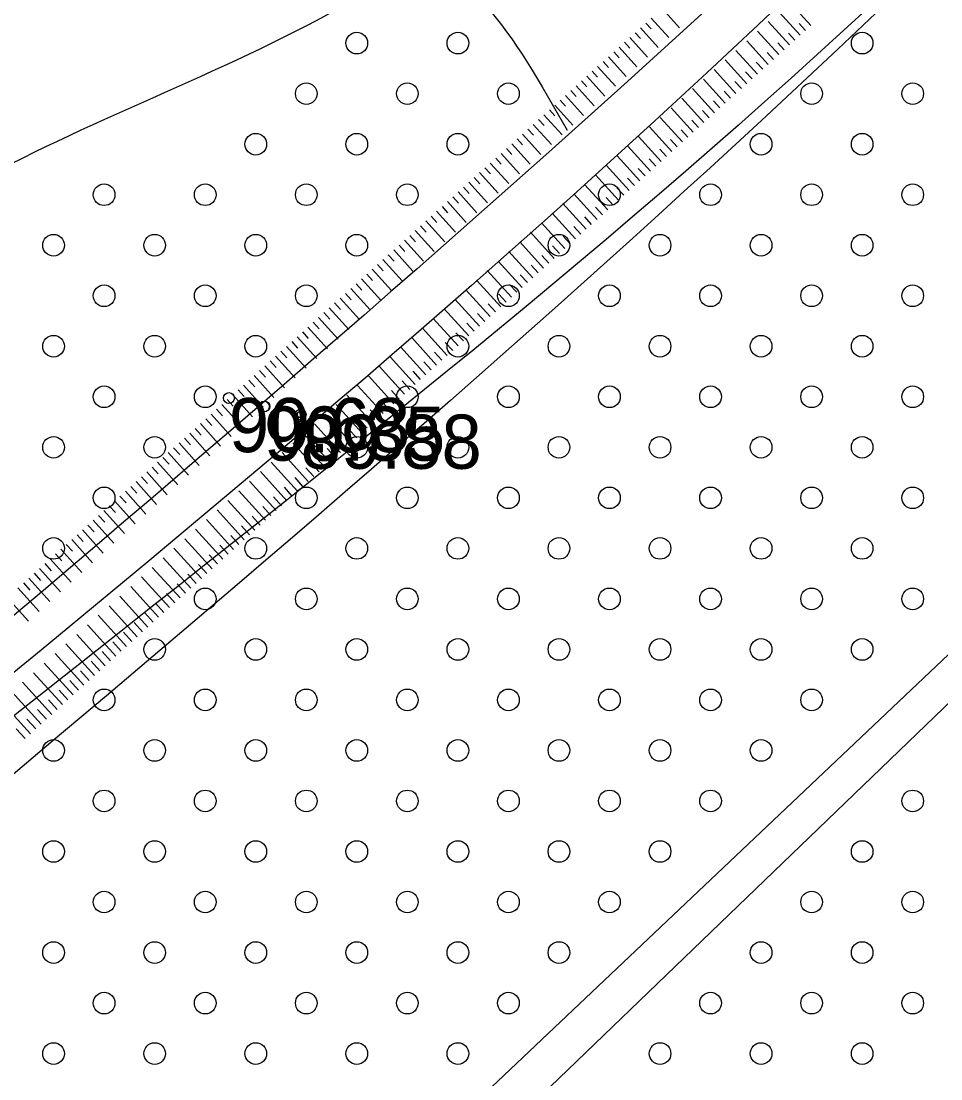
# Model space of a CAD drawing. Extents: x 316000 to 728450, y 314368 to 726000.
# Drawn here: x 725638.8 to 725702.4, y 315523.2 to 315596.5 of the extents above; entities that cross this region are included whole.
import ezdxf

# ---------------------------------------------------------------- set-up
doc = ezdxf.new("R2010")
doc.units = 0
for name, color, linetype in [('HIDG_ELEM_####_####_#', 7, 'Continuous'), ('HIDG_GRAV_####_####_#', 7, 'Continuous'), ('RELJ_AATZ_####_TKST_#', 7, 'Continuous'), ('RELJ_ELEM_####_####_#', 7, 'Continuous'), ('RELJ_NOGA_####_####_#', 7, 'Continuous'), ('TERT_ELEM_####_####_#', 7, 'Continuous'), ('TERT_KONT_####_####_#', 7, 'Continuous')]:
    doc.layers.add(name, color=color, linetype=linetype)

msp = doc.modelspace()

# ---------------------------------------------------------------- linework, layer by layer
at = {"layer": 'HIDG_ELEM_####_####_#'}
msp.add_circle((725658.106, 315569.264), 0.225, dxfattribs=at)
at = {"layer": 'HIDG_GRAV_####_####_#'}
msp.add_lwpolyline([(725748.973, 315596.209), (725751.0100204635, 315595.5121681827), (725643.1476843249, 315491.6312040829), (725641.4060000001, 315494.343), (725748.973, 315596.209)], dxfattribs=at)
for points in [[(725743.944, 315631.872), (725731.1800000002, 315638.5140000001), (725730.0588248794, 315638.4860084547), (725729.0416291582, 315637.5281018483), (725728.0741186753, 315636.1890738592), (725727.1019992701, 315635.017718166), (725611.6787771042, 315529.82054677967)], [(725741.1610000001, 315628.109), (725732.013, 315633.48000000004), (725729.3674430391, 315630.93907173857), (725612.6699933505, 315527.51301727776), (725555.2138402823, 315474.3075427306)]]:
    msp.add_spline(points, degree=3, dxfattribs=at)
at = {"layer": 'RELJ_ELEM_####_####_#'}
for centre in [(725653.1460000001, 315570.414), (725655.572, 315569.825), (725655.606, 315569.829), (725658.106, 315569.264)]:
    msp.add_circle(centre, 0.375, dxfattribs=at)
at = {"layer": 'RELJ_NOGA_####_####_#'}
for p, q in [((725683.1404815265, 315597.39670044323), (725684.3494049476, 315596.05283824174)), ((725693.4445708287, 315596.2198231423), (725691.9950560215, 315597.8168523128)), ((725682.3970354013, 315596.72790461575), (725683.6103007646, 315595.3792158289)), ((725692.7040932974, 315595.547742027), (725691.2466238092, 315597.1535354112)), ((725681.653589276, 315596.05910878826), (725682.8711965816, 315594.7055934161)), ((725682.0253123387, 315596.39350670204), (725682.3899432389, 315595.9881760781)), ((725691.2231382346, 315594.2035797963), (725689.7497593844, 315595.82690160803)), ((725691.963615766, 315594.8756609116), (725690.4981915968, 315596.4902185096)), ((725693.0743320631, 315595.88378258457), (725692.6382844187, 315596.3642059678)), ((725680.5384200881, 315595.055915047), (725680.9056561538, 315594.64768847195)), ((725680.9101431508, 315595.3903129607), (725682.1320923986, 315594.0319710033)), ((725681.2818662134, 315595.7247108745), (725681.6477996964, 315595.317932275)), ((725690.4826607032, 315593.53149868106), (725689.0013271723, 315595.1635847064)), ((725692.3338545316, 315595.2117014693), (725691.8954204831, 315595.69475411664)), ((725679.7949739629, 315594.3871192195), (725680.1635126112, 315593.9774446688)), ((725680.1666970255, 315594.72151713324), (725681.3929882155, 315593.3583485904)), ((725689.7421831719, 315592.85941756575), (725688.2528949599, 315594.50026780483)), ((725690.852899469, 315593.8675392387), (725690.4096926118, 315594.35585041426)), ((725691.5933770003, 315594.539620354), (725691.1525565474, 315595.0253022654)), ((725679.0515278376, 315593.71832339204), (725679.4213690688, 315593.30720086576)), ((725679.4232509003, 315594.05272130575), (725680.6538840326, 315592.6847261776)), ((725689.0017056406, 315592.18733645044), (725687.5044627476, 315593.83695090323)), ((725690.1124219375, 315593.1954581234), (725689.666828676, 315593.6863985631)), ((725678.3080817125, 315593.0495275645), (725678.6792255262, 315592.63695706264)), ((725678.679804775, 315593.38392547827), (725679.9147798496, 315592.01110376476)), ((725688.2612281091, 315591.51525533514), (725686.7560305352, 315593.1736340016)), ((725689.3719444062, 315592.5233770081), (725688.9239647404, 315593.01694671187)), ((725677.5646355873, 315592.380731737), (725677.9370819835, 315591.9667132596)), ((725677.9363586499, 315592.7151296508), (725679.1756756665, 315591.337481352)), ((725687.5207505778, 315590.8431742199), (725686.0075983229, 315592.51031710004)), ((725688.6314668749, 315591.8512958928), (725688.1811008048, 315592.34749486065)), ((725676.821189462, 315591.7119359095), (725677.194938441, 315591.2964694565)), ((725677.1929125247, 315592.0463338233), (725678.4365714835, 315590.66385893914)), ((725686.7802730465, 315590.1710931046), (725685.2591661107, 315591.84700019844)), ((725687.8909893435, 315591.1792147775), (725687.4382368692, 315591.6780430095)), ((725675.7060202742, 315590.7087421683), (725676.9583631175, 315589.3166141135)), ((725676.0777433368, 315591.04314008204), (725676.4527948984, 315590.62622565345)), ((725676.4494663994, 315591.3775379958), (725677.6974673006, 315589.9902365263)), ((725686.039795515, 315589.4990119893), (725684.5107338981, 315591.18368329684)), ((725687.1505118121, 315590.5071336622), (725686.6953729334, 315591.0085911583)), ((725674.962574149, 315590.0399463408), (725676.2192589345, 315588.64299170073)), ((725675.3342972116, 315590.3743442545), (725675.7106513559, 315589.95598185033)), ((725685.2993179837, 315588.8269308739), (725683.762301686, 315590.5203663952)), ((725686.4100342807, 315589.83505254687), (725685.9525089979, 315590.33913930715)), ((725674.2191280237, 315589.3711505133), (725675.4801547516, 315587.9693692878)), ((725674.5908510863, 315589.705548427), (725674.9685078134, 315589.2857380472)), ((725683.8183629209, 315587.48276864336), (725682.2654372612, 315589.193732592)), ((725684.5588404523, 315588.15484975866), (725683.0138694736, 315589.85704949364)), ((725685.6695567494, 315589.1629714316), (725685.2096450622, 315589.6696874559)), ((725673.4756818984, 315588.7023546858), (725674.7410505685, 315587.295746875)), ((725673.847404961, 315589.0367525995), (725674.2263642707, 315588.6154942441)), ((725683.0778853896, 315586.81068752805), (725681.5170050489, 315588.5304156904)), ((725684.929079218, 315588.4908903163), (725684.4667811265, 315589.0002356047)), ((725672.7322357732, 315588.0335588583), (725674.0019463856, 315586.62212446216)), ((725673.1039588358, 315588.36795677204), (725673.4842207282, 315587.94525044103)), ((725682.3374078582, 315586.13860641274), (725680.7685728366, 315587.86709878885)), ((725684.1886016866, 315587.818809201), (725683.7239171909, 315588.33078375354)), ((725671.6170665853, 315587.03036511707), (725671.999933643, 315586.6047628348)), ((725671.988789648, 315587.3647630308), (725673.2628422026, 315585.9485020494)), ((725672.3605127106, 315587.6991609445), (725672.7420771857, 315587.2750066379)), ((725681.5969303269, 315585.46652529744), (725680.0201406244, 315587.20378188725)), ((725682.7076466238, 315586.4746469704), (725682.2381893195, 315586.99188005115)), ((725683.4481241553, 315587.1467280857), (725682.9810532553, 315587.6613319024)), ((725670.8736204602, 315586.3615692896), (725671.2577901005, 315585.9345190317)), ((725671.2453435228, 315586.6959672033), (725672.5237380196, 315585.27487963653)), ((725680.8564527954, 315584.7944441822), (725679.271708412, 315586.54046498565)), ((725681.9671690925, 315585.8025658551), (725681.4953253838, 315586.3224282)), ((725670.130174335, 315585.6927734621), (725670.5156465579, 315585.26427522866)), ((725670.5018973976, 315586.0271713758), (725671.7846338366, 315584.6012572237)), ((725680.1159752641, 315584.1223630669), (725678.5232761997, 315585.87714808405)), ((725681.2266915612, 315585.1304847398), (725680.7524614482, 315585.6529763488)), ((725669.3867282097, 315585.02397763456), (725669.7735030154, 315584.59403142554)), ((725669.7584512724, 315585.3583755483), (725671.0455296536, 315583.9276348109)), ((725679.3754977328, 315583.4502819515), (725677.7748439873, 315585.21383118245)), ((725680.4862140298, 315584.4584036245), (725680.0095975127, 315584.9835244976)), ((725668.6432820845, 315584.35518180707), (725669.0313594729, 315583.9237876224)), ((725669.0150051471, 315584.6895797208), (725670.3064254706, 315583.2540123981)), ((725678.6350202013, 315582.77820083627), (725677.0264117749, 315584.5505142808)), ((725679.7457364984, 315583.78632250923), (725679.2667335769, 315584.3140726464)), ((725667.5281128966, 315583.3519880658), (725668.8282171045, 315581.9067675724)), ((725667.8998359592, 315583.6863859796), (725668.2892159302, 315583.25354381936)), ((725668.2715590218, 315584.0207838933), (725669.5673212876, 315582.5803899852)), ((725677.89454267, 315582.10611972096), (725676.2779795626, 315583.8871973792)), ((725679.005258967, 315583.1142413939), (725678.5238696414, 315583.6446207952)), ((725666.7846667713, 315582.6831922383), (725668.0891129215, 315581.2331451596)), ((725667.156389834, 315583.0175901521), (725667.5470723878, 315582.5833000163)), ((725677.1540651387, 315581.43403860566), (725675.5295473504, 315583.22388047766)), ((725678.2647814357, 315582.4421602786), (725677.7810057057, 315582.97516894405)), ((725666.0412206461, 315582.01439641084), (725667.3500087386, 315580.5595227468)), ((725666.4129437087, 315582.3487943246), (725666.8049288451, 315581.9130562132)), ((725675.6731100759, 315580.08987637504), (725674.0326829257, 315581.8972466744)), ((725676.4135876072, 315580.76195749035), (725674.781115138, 315582.560563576)), ((725677.5243039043, 315581.7700791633), (725677.0381417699, 315582.3057170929)), ((725665.2977745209, 315581.34560058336), (725666.6109045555, 315579.88590033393)), ((725665.6694975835, 315581.6799984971), (725666.0627853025, 315581.24281241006)), ((725674.9326325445, 315579.4177952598), (725673.2842507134, 315581.2339297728)), ((725676.7838263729, 315581.09799804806), (725676.2952778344, 315581.63626524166)), ((725664.5543283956, 315580.6768047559), (725665.8718003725, 315579.2122779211)), ((725664.9260514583, 315581.0112026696), (725665.32064176, 315580.572568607)), ((725674.1921550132, 315578.7457141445), (725672.5358185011, 315580.5706128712)), ((725676.0433488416, 315580.4259169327), (725675.5524138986, 315580.96681339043)), ((725663.4391592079, 315579.6736110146), (725663.836354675, 315579.2320810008)), ((725663.8108822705, 315580.0080089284), (725665.1326961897, 315578.5386555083)), ((725664.182605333, 315580.3424068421), (725664.5784982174, 315579.9023248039)), ((725673.4516774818, 315578.0736330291), (725671.7873862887, 315579.9072959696)), ((725675.3028713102, 315579.7538358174), (725674.809549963, 315580.29736153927)), ((725662.6957130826, 315579.0048151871), (725663.0942111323, 315578.56183719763)), ((725663.0674361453, 315579.33921310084), (725664.3935920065, 315577.86503309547)), ((725672.7111999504, 315577.4015519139), (725671.0389540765, 315579.243979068)), ((725673.8219162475, 315578.40967358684), (725673.3238220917, 315578.9584578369)), ((725674.5623937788, 315579.0817547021), (725674.0666860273, 315579.62790968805)), ((725661.9522669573, 315578.3360193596), (725662.3520675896, 315577.89159339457)), ((725662.32399002, 315578.67041727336), (725663.6544878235, 315577.1914106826)), ((725671.9707224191, 315576.7294707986), (725670.2905218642, 315578.5806621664)), ((725673.0814387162, 315577.73759247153), (725672.5809581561, 315578.2890059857)), ((725661.2088208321, 315577.6672235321), (725661.6099240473, 315577.2213495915)), ((725661.5805438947, 315578.0016214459), (725662.9153836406, 315576.51778826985)), ((725671.2302448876, 315576.05738968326), (725669.5420896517, 315577.9173452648)), ((725672.3409611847, 315577.0655113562), (725671.8380942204, 315577.61955413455)), ((725660.4653747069, 315576.9984277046), (725660.8677805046, 315576.5511057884)), ((725660.8370977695, 315577.3328256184), (725662.1762794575, 315575.844165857)), ((725670.4897673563, 315575.38530856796), (725668.7936574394, 315577.25402836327)), ((725671.6004836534, 315576.3934302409), (725671.0952302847, 315576.9501022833)), ((725659.7219285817, 315576.32963187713), (725660.125636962, 315575.88086198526)), ((725660.0936516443, 315576.6640297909), (725661.4371752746, 315575.17054344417)), ((725669.749289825, 315574.71322745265), (725668.0452252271, 315576.5907114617)), ((725670.860006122, 315575.7213491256), (725670.3523663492, 315576.28065043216)), ((725658.6067593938, 315575.3264381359), (725659.9589669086, 315573.82329861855)), ((725658.9784824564, 315575.66083604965), (725659.3834934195, 315575.2106181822)), ((725659.350205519, 315575.99523396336), (725660.6980710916, 315574.4969210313)), ((725669.0088122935, 315574.0411463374), (725667.2967930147, 315575.92739456)), ((725670.1195285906, 315575.0492680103), (725669.6095024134, 315575.61119858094)), ((725657.8633132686, 315574.6576423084), (725659.2198627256, 315573.1496762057)), ((725658.2350363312, 315574.99204022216), (725658.641349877, 315574.54037437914)), ((725667.5278572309, 315572.69698410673), (725665.7999285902, 315574.6007607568)), ((725668.2683347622, 315573.3690652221), (725666.5483608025, 315575.2640776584)), ((725669.3790510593, 315574.377186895), (725668.8666384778, 315574.9417467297)), ((725657.1198671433, 315573.9888464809), (725658.4807585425, 315572.4760537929)), ((725657.491590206, 315574.3232443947), (725657.8992063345, 315573.8701305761)), ((725666.7873796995, 315572.0249029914), (725665.0514963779, 315573.9374438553)), ((725668.6385735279, 315573.7051057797), (725668.1237745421, 315574.2722948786)), ((725656.376421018, 315573.32005065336), (725657.7416543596, 315571.80243138)), ((725656.7481440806, 315573.6544485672), (725657.1570627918, 315573.19988677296)), ((725666.0469021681, 315571.3528218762), (725664.3030641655, 315573.2741269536)), ((725667.8980959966, 315573.03302466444), (725667.3809106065, 315573.6028430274)), ((725655.6329748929, 315572.6512548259), (725657.0025501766, 315571.12880896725)), ((725656.0046979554, 315572.98565273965), (725656.4149192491, 315572.52964296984)), ((725665.3064246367, 315570.6807407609), (725663.5546319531, 315572.610810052)), ((725667.1576184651, 315572.36094354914), (725666.6380466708, 315572.93339117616)), ((725654.517805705, 315571.6480610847), (725654.9306321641, 315571.18915536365)), ((725654.8895287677, 315571.9824589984), (725656.2634459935, 315570.4551865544)), ((725655.2612518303, 315572.31685691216), (725655.6727757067, 315571.8593991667)), ((725664.5659471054, 315570.00865964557), (725662.806199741, 315571.9474931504)), ((725666.4171409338, 315571.68886243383), (725665.8951827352, 315572.263939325)), ((725653.7743595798, 315570.9792652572), (725654.1884886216, 315570.5189115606)), ((725654.1460826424, 315571.3136631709), (725655.5243418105, 315569.78156414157)), ((725663.825469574, 315569.33657853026), (725662.0577675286, 315571.2841762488)), ((725664.936185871, 315570.3447002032), (725664.4094548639, 315570.9250356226)), ((725665.6766634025, 315571.0167813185), (725665.1523187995, 315571.59448747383)), ((725653.0309134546, 315570.31046942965), (725653.446345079, 315569.84866775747)), ((725653.4026365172, 315570.6448673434), (725654.7852376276, 315569.1079417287)), ((725663.0849920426, 315568.664497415), (725661.3093353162, 315570.6208593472)), ((725664.1957083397, 315569.6726190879), (725663.6665909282, 315570.25558377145)), ((725652.2874673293, 315569.64167360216), (725652.7042015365, 315569.17842395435)), ((725652.659190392, 315569.97607151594), (725654.0461334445, 315568.43431931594)), ((725662.3445145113, 315567.9924162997), (725660.5609031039, 315569.9575424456)), ((725663.4552308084, 315569.0005379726), (725662.9237269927, 315569.5861319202)), ((725651.5440212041, 315568.9728777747), (725651.962057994, 315568.5081801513)), ((725651.9157442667, 315569.30727568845), (725653.3070292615, 315567.76069690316)), ((725661.60403698, 315567.32033518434), (725659.8124708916, 315569.294225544)), ((725662.7147532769, 315568.3284568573), (725662.1808630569, 315568.91668006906)), ((725650.4288520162, 315567.9696840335), (725651.8288208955, 315566.4134520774)), ((725650.8005750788, 315568.3040819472), (725651.2199144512, 315567.8379363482)), ((725651.1722981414, 315568.63847986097), (725652.5679250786, 315567.08707449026)), ((725660.1230819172, 315565.9761729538), (725658.3156064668, 315567.96759174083)), ((725660.8635594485, 315566.64825406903), (725659.0640386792, 315568.63090864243)), ((725661.9742757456, 315567.656375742), (725661.4379991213, 315568.24722821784)), ((725649.6854058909, 315567.30088820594), (725651.0897167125, 315565.73982966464)), ((725650.0571289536, 315567.63528611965), (725650.4777709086, 315567.1676925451)), ((725659.3826043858, 315565.3040918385), (725657.5671742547, 315567.30427483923)), ((725661.2337982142, 315566.98429462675), (725660.6951351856, 315567.57777636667)), ((725648.9419597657, 315566.63209237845), (725650.3506125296, 315565.0662072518)), ((725649.3136828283, 315566.96649029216), (725649.7356273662, 315566.497448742)), ((725658.6421268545, 315564.6320107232), (725656.8187420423, 315566.6409579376)), ((725660.4933206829, 315566.31221351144), (725659.95227125, 315566.9083245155)), ((725648.1985136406, 315565.96329655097), (725649.6115083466, 315564.39258483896)), ((725648.5702367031, 315566.2976944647), (725648.9934838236, 315565.8272049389)), ((725657.9016493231, 315563.95992960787), (725656.0703098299, 315565.97764103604)), ((725659.7528431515, 315565.64013239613), (725659.2094073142, 315566.23887266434)), ((725647.4550675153, 315565.2945007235), (725648.8724041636, 315563.7189624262)), ((725647.826790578, 315565.6288986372), (725648.2513402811, 315565.15696113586)), ((725657.1611717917, 315563.2878484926), (725655.3218776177, 315565.31432413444)), ((725659.0123656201, 315564.9680512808), (725658.4665433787, 315565.5694208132)), ((725646.3398983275, 315564.2913069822), (725646.767053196, 315563.8164735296)), ((725646.7116213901, 315564.62570489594), (725648.1332999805, 315563.04534001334)), ((725647.0833444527, 315564.9601028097), (725647.5091967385, 315564.48671733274)), ((725656.4206942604, 315562.6157673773), (725654.5734454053, 315564.65100723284)), ((725658.2718880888, 315564.2959701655), (725657.723679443, 315564.8999689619)), ((725645.5964522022, 315563.62251115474), (725646.0249096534, 315563.1462297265)), ((725645.9681752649, 315563.95690906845), (725647.3941957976, 315562.3717176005)), ((725655.6802167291, 315561.94368626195), (725653.825013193, 315563.9876903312)), ((725656.7909330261, 315562.9518079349), (725656.2379515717, 315563.5610652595)), ((725657.5314105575, 315563.6238890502), (725656.9808155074, 315564.2305171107)), ((725644.853006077, 315562.95371532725), (725645.2827661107, 315562.47598592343)), ((725645.2247291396, 315563.28811324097), (725646.6550916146, 315561.6980951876)), ((725654.9397391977, 315561.27160514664), (725653.0765809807, 315563.3243734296)), ((725656.0504554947, 315562.2797268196), (725655.495087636, 315562.89161340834)), ((725644.1095599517, 315562.28491949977), (725644.5406225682, 315561.8057421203)), ((725644.4812830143, 315562.6193174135), (725645.9159874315, 315561.0244727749)), ((725654.1992616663, 315560.5995240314), (725652.3281487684, 315562.66105652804)), ((725655.3099779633, 315561.60764570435), (725654.7522237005, 315562.2221615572)), ((725643.3661138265, 315561.6161236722), (725643.7984790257, 315561.1354983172)), ((725643.7378368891, 315561.950521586), (725645.1768832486, 315560.35085036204)), ((725653.458784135, 315559.9274429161), (725651.579716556, 315561.99773962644)), ((725654.569500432, 315560.93556458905), (725654.0093597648, 315561.552709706)), ((725642.2509446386, 315560.61292993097), (725643.6986748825, 315559.00360553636)), ((725642.6226677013, 315560.94732784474), (725643.0563354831, 315560.4652545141)), ((725642.9943907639, 315561.28172575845), (725644.4377790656, 315559.6772279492)), ((725651.9778290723, 315558.5832806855), (725650.0828521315, 315560.67110582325)), ((725652.7183066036, 315559.2553618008), (725650.8312843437, 315561.3344227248)), ((725653.8290229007, 315560.26348347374), (725653.2664958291, 315560.8832578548)), ((725641.5074985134, 315559.9441341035), (725642.9595706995, 315558.3299831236)), ((725641.879221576, 315560.27853201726), (725642.3141919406, 315559.79501071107)), ((725651.2373515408, 315557.91119957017), (725649.3344199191, 315560.0077889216)), ((725653.0885453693, 315559.5914023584), (725652.5236318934, 315560.21380600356)), ((725640.7640523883, 315559.275338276), (725642.2204665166, 315557.6563607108)), ((725641.1357754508, 315559.60973618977), (725641.572048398, 315559.124766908)), ((725650.4968740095, 315557.2391184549), (725648.5859877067, 315559.34447202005)), ((725652.3480678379, 315558.9193212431), (725651.7807679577, 315559.54435415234)), ((725640.020606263, 315558.6065424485), (725641.4813623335, 315556.98273829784)), ((725640.3923293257, 315558.9409403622), (725640.8299048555, 315558.4545231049)), ((725649.7563964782, 315556.56703733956), (725647.8375554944, 315558.68115511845)), ((725651.6075903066, 315558.2472401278), (725651.0379040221, 315558.8749023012)), ((725639.2771601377, 315557.937746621), (725640.7422581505, 315556.30911588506)), ((725639.6488832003, 315558.27214453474), (725640.0877613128, 315557.78427930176)), ((725649.0159189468, 315555.89495622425), (725647.0891232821, 315558.01783821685)), ((725650.8671127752, 315557.5751590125), (725650.2950400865, 315558.20545045)), ((725638.5337140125, 315557.26895079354), (725640.0031539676, 315555.6354934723)), ((725638.9054370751, 315557.60334870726), (725639.3456177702, 315557.1140354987)), ((725648.2754414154, 315555.222875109), (725646.3406910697, 315557.3545213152)), ((725650.1266352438, 315556.9030778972), (725649.5521761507, 315557.53599859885)), ((725637.7902678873, 315556.60015496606), (725639.2640497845, 315554.96187105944)), ((725647.534963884, 315554.5507939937), (725645.5922588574, 315556.6912044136)), ((725649.3861577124, 315556.23099678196), (725648.8093122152, 315556.8665467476)), ((725646.7944863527, 315553.8787128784), (725644.8438266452, 315556.02788751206)), ((725647.9052026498, 315554.88683455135), (725647.3235843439, 315555.5276430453)), ((725648.6456801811, 315555.55891566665), (725648.0664482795, 315556.19709489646)), ((725646.0540088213, 315553.2066317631), (725644.0953944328, 315555.3645706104)), ((725647.1647251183, 315554.214753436), (725646.5807204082, 315554.8581911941)), ((725644.5730537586, 315551.8624695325), (725642.5985300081, 315554.03793680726)), ((725645.3135312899, 315552.5345506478), (725643.3469622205, 315554.7012537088)), ((725646.424247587, 315553.54267232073), (725645.8378564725, 315554.18873934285)), ((725643.8325762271, 315551.19038841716), (725641.8500977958, 315553.3746199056)), ((725645.6837700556, 315552.8705912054), (725645.0949925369, 315553.5192874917)), ((725643.0920986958, 315550.51830730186), (725641.1016655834, 315552.71130300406)), ((725644.9432925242, 315552.1985100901), (725644.3521286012, 315552.8498356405)), ((725642.3516211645, 315549.84622618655), (725640.3532333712, 315552.04798610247)), ((725644.2028149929, 315551.5264289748), (725643.6092646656, 315552.1803837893)), ((725641.6111436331, 315549.1741450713), (725639.6048011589, 315551.38466920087)), ((725643.4623374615, 315550.85434785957), (725642.86640073, 315551.51093193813)), ((725640.8706661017, 315548.502063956), (725638.8563689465, 315550.7213522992)), ((725642.7218599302, 315550.18226674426), (725642.1235367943, 315550.84148008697)), ((725640.1301885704, 315547.8299828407), (725638.1079367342, 315550.0580353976)), ((725641.9813823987, 315549.51018562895), (725641.3806728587, 315550.17202823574)), ((725639.389711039, 315547.1579017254), (725637.3595045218, 315549.39471849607)), ((725641.2409048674, 315548.8381045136), (725640.637808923, 315549.5025763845)), ((725639.7599498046, 315547.49394228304), (725639.1520810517, 315548.16367268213)), ((725640.5004273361, 315548.16602339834), (725639.8949449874, 315548.83312453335)), ((725639.0194722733, 315546.82186116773), (725638.409217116, 315547.49422083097))]:
    msp.add_line(p, q, dxfattribs=at)
for points in [[(725744.701, 315632.911), (725731.2122469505, 315640.0386943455), (725729.056271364, 315639.5840256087), (725728.3072907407, 315638.79600724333), (725727.6980921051, 315637.94217499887), (725727.1090350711, 315637.09598736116), (725726.4204792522, 315636.33090281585), (725610.4090988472, 315531.96836123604)], [(725740.8620000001, 315626.984), (725732.496455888, 315631.1419358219), (725731.675729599, 315631.1475109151), (725730.9005735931, 315630.5492934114), (725730.162049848, 315629.6870659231), (725729.4512203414, 315628.90061106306), (725614.9961785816, 315525.0175506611)]]:
    msp.add_spline(points, degree=3, dxfattribs=at)
at = {"layer": 'TERT_ELEM_####_####_#'}
for centre in [(725662, 315595), (725669, 315595), (725697, 315595), (725658.5, 315591.5), (725665.5, 315591.5), (725672.5, 315591.5), (725693.5, 315591.5), (725700.5, 315591.5), (725655, 315588), (725662, 315588), (725669, 315588), (725690, 315588), (725697, 315588), (725644.5, 315584.5), (725651.5, 315584.5), (725658.5, 315584.5), (725665.5, 315584.5), (725679.5, 315584.5), (725686.5, 315584.5), (725693.5, 315584.5), (725700.5, 315584.5), (725641, 315581), (725648, 315581), (725655, 315581), (725662, 315581), (725676, 315581), (725683, 315581), (725690, 315581), (725697, 315581), (725644.5, 315577.5), (725651.5, 315577.5), (725658.5, 315577.5), (725672.5, 315577.5), (725679.5, 315577.5), (725686.5, 315577.5), (725693.5, 315577.5), (725700.5, 315577.5), (725641, 315574), (725648, 315574), (725655, 315574), (725669, 315574), (725676, 315574), (725683, 315574), (725690, 315574), (725697, 315574), (725644.5, 315570.5), (725651.5, 315570.5), (725665.5, 315570.5), (725672.5, 315570.5), (725679.5, 315570.5), (725686.5, 315570.5), (725693.5, 315570.5), (725700.5, 315570.5), (725641, 315567), (725648, 315567), (725662, 315567), (725669, 315567), (725676, 315567), (725683, 315567), (725690, 315567), (725697, 315567), (725644.5, 315563.5), (725658.5, 315563.5), (725665.5, 315563.5), (725672.5, 315563.5), (725679.5, 315563.5), (725686.5, 315563.5), (725693.5, 315563.5), (725700.5, 315563.5), (725641, 315560), (725655, 315560), (725662, 315560), (725669, 315560), (725676, 315560), (725683, 315560), (725690, 315560), (725697, 315560), (725651.5, 315556.5), (725658.5, 315556.5), (725665.5, 315556.5), (725672.5, 315556.5), (725679.5, 315556.5), (725686.5, 315556.5), (725693.5, 315556.5), (725700.5, 315556.5), (725648, 315553), (725655, 315553), (725662, 315553), (725669, 315553), (725676, 315553), (725683, 315553), (725690, 315553), (725697, 315553), (725644.5, 315549.5), (725651.5, 315549.5), (725658.5, 315549.5), (725665.5, 315549.5), (725672.5, 315549.5), (725679.5, 315549.5), (725686.5, 315549.5), (725693.5, 315549.5), (725641, 315546), (725648, 315546), (725655, 315546), (725662, 315546), (725669, 315546), (725676, 315546), (725683, 315546), (725690, 315546), (725644.5, 315542.5), (725651.5, 315542.5), (725658.5, 315542.5), (725665.5, 315542.5), (725672.5, 315542.5), (725679.5, 315542.5), (725686.5, 315542.5), (725700.5, 315542.5), (725641, 315539), (725648, 315539), (725655, 315539), (725662, 315539), (725669, 315539), (725676, 315539), (725683, 315539), (725697, 315539), (725644.5, 315535.5), (725651.5, 315535.5), (725658.5, 315535.5), (725665.5, 315535.5), (725672.5, 315535.5), (725679.5, 315535.5), (725693.5, 315535.5), (725700.5, 315535.5), (725641, 315532), (725648, 315532), (725655, 315532), (725662, 315532), (725669, 315532), (725676, 315532), (725690, 315532), (725697, 315532), (725644.5, 315528.5), (725651.5, 315528.5), (725658.5, 315528.5), (725665.5, 315528.5), (725672.5, 315528.5), (725686.5, 315528.5), (725693.5, 315528.5), (725700.5, 315528.5), (725641, 315525), (725648, 315525), (725655, 315525), (725662, 315525), (725669, 315525), (725683, 315525), (725690, 315525), (725697, 315525)]:
    msp.add_circle(centre, 0.75, dxfattribs=at)
at = {"layer": 'TERT_KONT_####_####_#'}
msp.add_spline([(725558.0731425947, 315596.3970132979), (725580.659, 315581.819), (725609.8680328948, 315563.59752923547), (725611.239, 315562.656), (725613.5676467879, 315564.9148792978), (725663.6488964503, 315599.09665422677), (725664.6070000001, 315599.647), (725676.5716713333, 315588.96418172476)], degree=3, dxfattribs=at)

# ---------------------------------------------------------------- texts
at = {"layer": 'RELJ_AATZ_####_TKST_#'}
for s, p in [('90.68', (725653.1460000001, 315566.664)), ('90.35', (725655.572, 315566.075)), ('89.88', (725658.106, 315565.514))]:
    msp.add_text(s, height=3.75, dxfattribs=at).set_placement(p)

doc.saveas('drawing.dxf')
